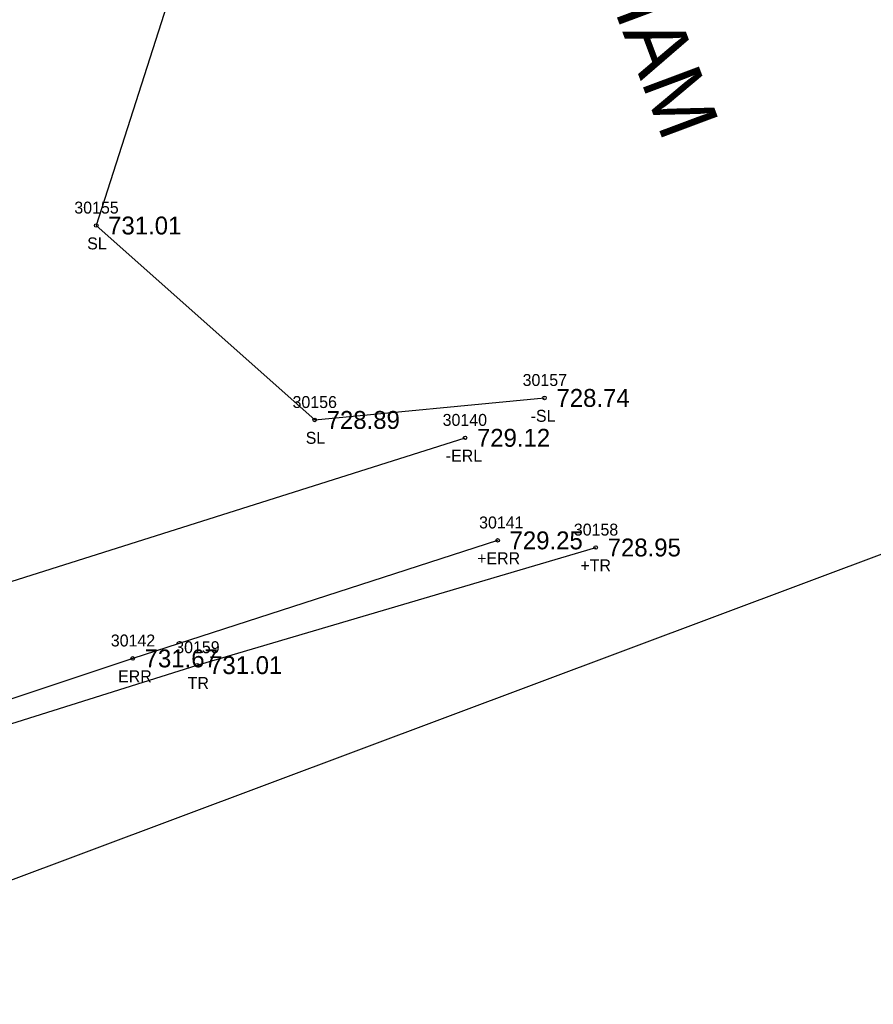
# Model space of a CAD drawing. Extents: x 1375131 to 1378678, y 999028 to 1004053.
# Drawn here: x 1376947 to 1377018.5, y 1002476.7 to 1002559.2 of the extents above; entities that cross this region are included whole.
import ezdxf

# ---------------------------------------------------------------- set-up
doc = ezdxf.new("R2010")
doc.units = 0
for name, color, linetype in [('RD_EX_DV_Prop', 7, 'Continuous'), ('RD_EX_DV_TX_Prop(Owner ID)', 7, 'Continuous'), ('RD_EX_Road', 7, 'Continuous'), ('RD_EX_Road_txCode', 7, 'Continuous'), ('RD_EX_RW', 7, 'Continuous'), ('RD_EX_TX_Road_ELEV', 7, 'Continuous'), ('RD_EX_TX_VEG_ELEV', 7, 'Continuous'), ('RD_EX_VEG', 7, 'Continuous'), ('RD_EX_VEG_txCode', 7, 'Continuous'), ('RD_HC_Cl', 7, 'Continuous'), ('RD_SMD_Locator', 7, 'Continuous')]:
    doc.layers.add(name, color=color, linetype=linetype)

msp = doc.modelspace()

# ---------------------------------------------------------------- linework, layer by layer
at = {"layer": 'RD_EX_DV_Prop'}
msp.add_line((1376922.303, 1002478.143), (1377313.16, 1002624.462), dxfattribs=at)
at = {"layer": 'RD_EX_Road'}
for points in [[(1376908.742, 1002499.002), (1376930.889, 1002507.274), (1376984.297, 1002524.174)], [(1376987.029, 1002515.581), (1376956.453, 1002505.691), (1376933.246, 1002497.953), (1376914.607, 1002491.438)]]:
    msp.add_lwpolyline(points, dxfattribs=at)
for points in [[(1377013.314, 1002264.907), (1376982.808, 1002315.683), (1376952.468, 1002370.341), (1376923.174, 1002424.32), (1376895.644, 1002480.03), (1376870.11, 1002535.049), (1376846.329, 1002588.864), (1376822.292, 1002645.031), (1376786.564, 1002736.458)], [(1376994.747, 1002253.913), (1376964.909, 1002306.463), (1376934.396, 1002359.987), (1376904.773, 1002415.485), (1376877.271, 1002471.511), (1376851.037, 1002526.893), (1376827.48, 1002581.62), (1376804.191, 1002637.821), (1376768.457, 1002728.838)]]:
    msp.add_spline(points, degree=3, dxfattribs=at)
at = {"layer": 'RD_EX_RW'}
for radius in [2767, 2833]:
    msp.add_arc((1379404.86, 1003700.108), radius, 200.269954, 211.131166, dxfattribs=at)
at = {"layer": 'RD_EX_VEG'}
for points in [[(1376960.273, 1002563.422), (1376953.394, 1002541.963), (1376971.703, 1002525.672), (1376990.959, 1002527.517)], [(1377016.163, 1002440.332), (1376948.43, 1002386.71), (1376912.576, 1002489.618), (1376961.851, 1002505.127), (1376995.25, 1002514.983)]]:
    msp.add_lwpolyline(points, dxfattribs=at)
at = {"layer": 'RD_HC_Cl'}
msp.add_arc((1379404.86, 1003700.108), 2800, 200.269954, 211.131166, dxfattribs=at)
at = {"layer": 'RD_SMD_Locator'}
for centre in [(1376953.394, 1002541.963), (1376990.959, 1002527.517), (1376971.703, 1002525.672), (1376984.297, 1002524.174), (1376987.029, 1002515.581), (1376995.25, 1002514.983), (1376956.453, 1002505.691), (1376961.851, 1002505.127)]:
    msp.add_circle(centre, 0.15, dxfattribs=at)

# ---------------------------------------------------------------- texts
at = {"layer": 'RD_EX_DV_TX_Prop(Owner ID)'}
msp.add_text('ROGER & RENAE GILLIAM', height=5, rotation=290.50029, dxfattribs=at).set_placement((1376971.569, 1002627.481))
at = {"layer": 'RD_EX_Road_txCode'}
for s, p in [('30140', (1376982.423, 1002525.174)), ('-ERL', (1376982.683, 1002522.174)), ('30141', (1376985.478, 1002516.581)), ('+ERR', (1376985.312, 1002513.581)), ('30142', (1376954.618, 1002506.691)), ('ERR', (1376955.225, 1002503.691))]:
    msp.add_text(s, height=1, dxfattribs=at).set_placement(p)
at = {"layer": 'RD_EX_TX_Road_ELEV'}
for s, p in [('729.12', (1376985.297, 1002523.424)), ('729.25', (1376988.029, 1002514.831)), ('731.67', (1376957.453, 1002504.941))]:
    msp.add_text(s, height=1.5, dxfattribs=at).set_placement(p)
at = {"layer": 'RD_EX_TX_VEG_ELEV'}
for s, p in [('731.01', (1376954.394, 1002541.213)), ('728.74', (1376991.959, 1002526.767)), ('728.89', (1376972.703, 1002524.922)), ('728.95', (1376996.25, 1002514.233)), ('731.01', (1376962.851, 1002504.377))]:
    msp.add_text(s, height=1.5, dxfattribs=at).set_placement(p)
at = {"layer": 'RD_EX_VEG_txCode'}
for s, p in [('30155', (1376951.559, 1002542.963)), ('SL', (1376952.638, 1002539.963)), ('30157', (1376989.124, 1002528.517)), ('30156', (1376969.845, 1002526.672)), ('-SL', (1376989.794, 1002525.517)), ('SL', (1376970.947, 1002523.672)), ('30158', (1376993.415, 1002515.983)), ('+TR', (1376993.967, 1002512.983)), ('30159', (1376960.016, 1002506.127)), ('TR', (1376961.056, 1002503.127))]:
    msp.add_text(s, height=1, dxfattribs=at).set_placement(p)

doc.saveas('drawing.dxf')
